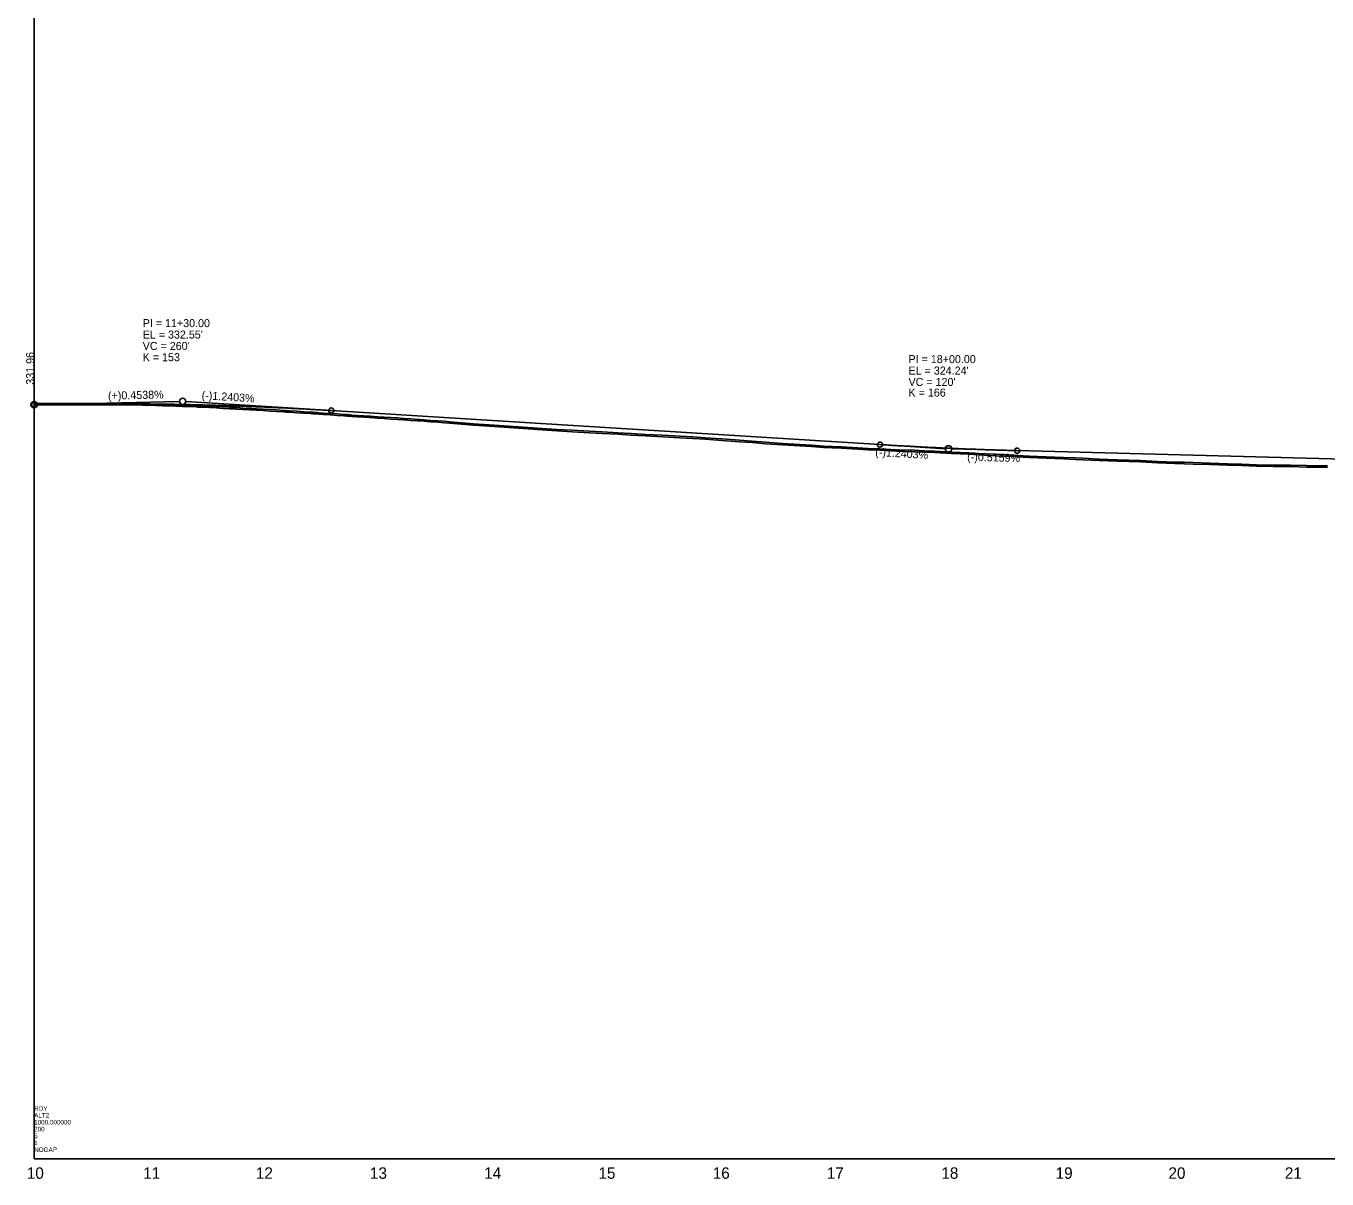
# Model space of a CAD drawing. Extents: x 2111382 to 2119088, y 667477 to 672158.
# Drawn here: x 2112692 to 2113830, y 667477 to 668486 of the extents above; entities that cross this region are included whole.
import ezdxf

# ---------------------------------------------------------------- set-up
doc = ezdxf.new("R2010")
doc.units = 0
for name, color, linetype in [('Exist Profile Cell', 7, 'Continuous'), ('Exist Vertical Profile Ground Line', 7, 'Continuous'), ('Exist Vertical Profile Horizontal Axis Label Major', 7, 'Continuous'), ('Prop Vertical Profile Curve Label', 7, 'Continuous'), ('Prop Vertical Profile Grade', 7, 'Continuous'), ('Prop Vertical Profile Grade Label', 7, 'Continuous'), ('Prop VPI Label', 7, 'Continuous'), ('Scratch_Level_2', 7, 'Continuous')]:
    doc.layers.add(name, color=color, linetype=linetype)

msp = doc.modelspace()

# ---------------------------------------------------------------- linework, layer by layer
at = {"layer": 'Exist Profile Cell'}
for q in [(2112699, 669494.5), (2114955.5, 667494.5), (2112699, 667494.5)]:
    msp.add_line((2112699, 667494.5), q, dxfattribs=at)
at = {"layer": 'Exist Vertical Profile Ground Line'}
for points in [[(2112699, 668154.3), (2112711.5, 668154.3), (2112717.4, 668154.3), (2112723.2, 668154.3), (2112729.1, 668154.3), (2112735, 668154.3), (2112740.8, 668154.3), (2112746.7, 668154.3), (2112752.6, 668154.3), (2112758.5, 668154.3), (2112759, 668154.3), (2112762.3, 668154.3), (2112764.3, 668154.3), (2112770.2, 668154.3), (2112776.1, 668154.2), (2112781.9, 668154.2), (2112785.4, 668154.2), (2112787.8, 668154.1), (2112793.7, 668153.9), (2112799.6, 668153.8), (2112805.4, 668153.6), (2112811.3, 668153.4), (2112814.5, 668153.3), (2112815.4, 668153.2), (2112816.2, 668153.2), (2112817.2, 668153.2), (2112823, 668153), (2112828.9, 668152.8), (2112834.8, 668152.6), (2112840.7, 668152.4), (2112842.2, 668152.3), (2112846.5, 668152.1), (2112852.4, 668151.8), (2112858.3, 668151.5), (2112864.2, 668151.1), (2112870, 668150.8), (2112870.4, 668150.8), (2112872.2, 668150.7), (2112875.9, 668150.5), (2112881.8, 668150.2), (2112887.6, 668149.9), (2112889.6, 668149.8), (2112893.1, 668149.5), (2112893.5, 668149.5), (2112899.4, 668149.2), (2112905.3, 668148.8), (2112911.1, 668148.4), (2112917, 668148.1), (2112919.6, 668147.9), (2112922.9, 668147.7), (2112928.7, 668147.3), (2112934.6, 668146.9), (2112940.5, 668146.6), (2112942.8, 668146.4), (2112946.4, 668146.2), (2112948.1, 668146), (2112952.2, 668145.8), (2112958.1, 668145.4), (2112964, 668145), (2112969.9, 668144.6), (2112972.8, 668144.4), (2112975.7, 668144.2), (2112977, 668144.1), (2112981.6, 668143.8), (2112987.5, 668143.4), (2112992.1, 668143.1), (2112993.3, 668143), (2112999.2, 668142.6), (2112999.6, 668142.6), (2113005.1, 668142.2), (2113011, 668141.8), (2113016.8, 668141.4), (2113022.1, 668141.1), (2113022.7, 668141), (2113028.6, 668140.6), (2113034.4, 668140.2), (2113036.4, 668140.1), (2113040.3, 668139.8), (2113043, 668139.6), (2113046.2, 668139.4), (2113052.1, 668139), (2113057.9, 668138.5), (2113062.5, 668138.2), (2113073, 668137.3), (2113083.5, 668136.4), (2113101.4, 668135.1), (2113114.3, 668134.3), (2113131.3, 668133.1), (2113143.3, 668132.2), (2113156.2, 668131.5), (2113169.6, 668130.7), (2113180, 668130.1), (2113195.9, 668129.2), (2113210, 668128.4), (2113221.4, 668127.8), (2113234, 668127.1), (2113248.9, 668126.3), (2113264, 668125.4), (2113275.4, 668124.8), (2113286.1, 668124.2), (2113300.7, 668123.1)], [(2113300.7, 668123.1), (2113316.1, 668121.9), (2113327.3, 668121.1), (2113338.9, 668120.2), (2113353.8, 668119.3), (2113368.9, 668118.2), (2113379.2, 668117.6), (2113389.6, 668116.9), (2113405.1, 668116.2), (2113419.6, 668115.4), (2113428.8, 668114.8), (2113438.9, 668114.4), (2113453.4, 668113.7), (2113468.9, 668113.2), (2113477.6, 668112.7), (2113486.8, 668112.4), (2113501.6, 668111.7), (2113516.8, 668110.9), (2113525.1, 668110.4), (2113539.8, 668109.6), (2113554.8, 668108.9), (2113564.4, 668108.4), (2113569.5, 668108.1), (2113584.5, 668107.4), (2113599.6, 668106.9), (2113609.8, 668106.4), (2113616.5, 668106.1), (2113631.2, 668105.6), (2113646.5, 668105), (2113656.8, 668104.5), (2113667, 668104.2), (2113681.9, 668103.5), (2113697, 668102.8), (2113705.4, 668102.7), (2113713.1, 668102.3), (2113728, 668101.9), (2113743.1, 668101.3), (2113755.7, 668101), (2113768.5, 668100.5), (2113782.9, 668100.2), (2113798.5, 668100.1), (2113812.1, 668099.8), (2113828.6, 668099.7), (2113830.4, 668099.7)]]:
    msp.add_lwpolyline(points, dxfattribs=at)
at = {"layer": 'Prop Vertical Profile Curve Label'}
for centre in [(2112699, 668154.3), (2112959, 668149.2), (2113439, 668119.4), (2113559, 668114.1)]:
    msp.add_circle(centre, 2.25, dxfattribs=at)
at = {"layer": 'Prop Vertical Profile Grade'}
for p, q in [((2112959, 668149.2), (2113439, 668119.4)), ((2113559, 668114.1), (2113879, 668105.9))]:
    msp.add_line(p, q, dxfattribs=at)
for points in [[(2112699, 668154.3), (2112704.2, 668154.4), (2112709.4, 668154.5), (2112714.6, 668154.6), (2112719.8, 668154.7), (2112725, 668154.8), (2112730.2, 668154.8), (2112735.4, 668154.9), (2112740.6, 668154.9), (2112745.8, 668155), (2112751, 668155), (2112756.2, 668155), (2112761.4, 668155.1), (2112766.6, 668155.1), (2112771.8, 668155.1), (2112777, 668155.1), (2112782.2, 668155), (2112787.4, 668155), (2112792.6, 668155), (2112797.8, 668154.9), (2112803, 668154.9), (2112808.2, 668154.8), (2112813.4, 668154.7), (2112818.6, 668154.7), (2112823.8, 668154.6), (2112829, 668154.5), (2112834.2, 668154.4), (2112839.4, 668154.2), (2112844.6, 668154.1), (2112849.8, 668154), (2112855, 668153.9), (2112860.2, 668153.7), (2112865.4, 668153.5), (2112870.6, 668153.4), (2112875.8, 668153.2), (2112881, 668153), (2112886.2, 668152.8), (2112891.4, 668152.6), (2112896.6, 668152.4), (2112901.8, 668152.2), (2112907, 668151.9), (2112912.2, 668151.7), (2112917.4, 668151.5), (2112922.6, 668151.2), (2112927.8, 668150.9), (2112933, 668150.7), (2112938.2, 668150.4), (2112943.4, 668150.1), (2112948.6, 668149.8), (2112953.8, 668149.5), (2112959, 668149.2)], [(2113439, 668119.4), (2113441.4, 668119.2), (2113443.8, 668119.1), (2113446.2, 668119), (2113448.6, 668118.8), (2113451, 668118.7), (2113453.4, 668118.5), (2113455.8, 668118.4), (2113458.2, 668118.3), (2113460.6, 668118.1), (2113463, 668118), (2113465.4, 668117.9), (2113467.8, 668117.7), (2113470.2, 668117.6), (2113472.6, 668117.5), (2113475, 668117.4), (2113477.4, 668117.2), (2113479.8, 668117.1), (2113482.2, 668117), (2113484.6, 668116.9), (2113487, 668116.8), (2113489.4, 668116.7), (2113491.8, 668116.5), (2113494.2, 668116.4), (2113496.6, 668116.3), (2113499, 668116.2), (2113501.4, 668116.1), (2113503.8, 668116), (2113506.2, 668115.9), (2113508.6, 668115.8), (2113511, 668115.7), (2113513.4, 668115.6), (2113515.8, 668115.5), (2113518.2, 668115.4), (2113520.6, 668115.3), (2113523, 668115.3), (2113525.4, 668115.2), (2113527.8, 668115.1), (2113530.2, 668115), (2113532.6, 668114.9), (2113535, 668114.8), (2113537.4, 668114.8), (2113539.8, 668114.7), (2113542.2, 668114.6), (2113544.6, 668114.5), (2113547, 668114.5), (2113549.4, 668114.4), (2113551.8, 668114.3), (2113554.2, 668114.3), (2113556.6, 668114.2), (2113559, 668114.1)]]:
    msp.add_spline(points, degree=3, dxfattribs=at)
at = {"layer": 'Prop VPI Label'}
for p, q in [((2112699, 668154.3), (2112826.3, 668157.2)), ((2112959, 668149.2), (2112831.7, 668157.1)), ((2113439, 668119.4), (2113496.3, 668115.8)), ((2113559, 668114.1), (2113501.8, 668115.6))]:
    msp.add_line(p, q, dxfattribs=at)
for centre in [(2112699, 668154.3), (2112829, 668157.2), (2113499, 668115.7)]:
    msp.add_circle(centre, 2.75, dxfattribs=at)
at = {"layer": 'Scratch_Level_2'}
for points in [[(2112699, 668155.5), (2112711.5, 668155.5), (2112717.4, 668155.5), (2112723.2, 668155.5), (2112729.1, 668155.5), (2112735, 668155.5), (2112740.8, 668155.5), (2112746.7, 668155.5), (2112752.6, 668155.5), (2112758.5, 668155.5), (2112759, 668155.5), (2112762.3, 668155.5), (2112764.3, 668155.5), (2112770.2, 668155.5), (2112776.1, 668155.5), (2112781.9, 668155.5), (2112785.4, 668155.5), (2112787.8, 668155.4), (2112793.7, 668155.2), (2112799.6, 668155), (2112805.4, 668154.8), (2112811.3, 668154.6), (2112814.5, 668154.5), (2112815.4, 668154.5), (2112816.2, 668154.5), (2112817.2, 668154.4), (2112823, 668154.2), (2112828.9, 668154), (2112834.8, 668153.8), (2112840.7, 668153.6), (2112842.2, 668153.5), (2112846.5, 668153.3), (2112852.4, 668153), (2112858.3, 668152.7), (2112864.2, 668152.4), (2112870, 668152.1), (2112870.4, 668152.1), (2112872.2, 668152), (2112875.9, 668151.8), (2112881.8, 668151.4), (2112887.6, 668151.1), (2112889.6, 668151), (2112893.1, 668150.8), (2112893.5, 668150.8), (2112899.4, 668150.4), (2112905.3, 668150), (2112911.1, 668149.7), (2112917, 668149.3), (2112919.6, 668149.1), (2112922.9, 668148.9), (2112928.7, 668148.6), (2112934.6, 668148.2), (2112940.5, 668147.8), (2112942.8, 668147.7), (2112946.4, 668147.4), (2112948.1, 668147.3), (2112952.2, 668147), (2112958.1, 668146.6), (2112964, 668146.2), (2112969.9, 668145.8), (2112972.8, 668145.6), (2112975.7, 668145.4), (2112977, 668145.3), (2112981.6, 668145), (2112987.5, 668144.6), (2112992.1, 668144.3), (2112993.3, 668144.2), (2112999.2, 668143.8), (2112999.6, 668143.8), (2113005.1, 668143.5), (2113011, 668143.1), (2113016.8, 668142.7), (2113022.1, 668142.3), (2113022.7, 668142.3), (2113028.6, 668141.9), (2113034.4, 668141.5), (2113036.4, 668141.3), (2113040.3, 668141.1), (2113043, 668140.9), (2113046.2, 668140.6), (2113052.1, 668140.2), (2113057.9, 668139.8), (2113062.5, 668139.4), (2113073, 668138.5), (2113083.5, 668137.7), (2113101.4, 668136.3), (2113114.3, 668135.6), (2113131.3, 668134.3), (2113143.3, 668133.5), (2113156.2, 668132.7), (2113169.6, 668131.9), (2113180, 668131.4), (2113195.9, 668130.5), (2113210, 668129.7), (2113221.4, 668129.1), (2113234, 668128.3), (2113248.9, 668127.6), (2113264, 668126.7), (2113275.4, 668126.1), (2113286.1, 668125.4), (2113300.7, 668124.4)], [(2113300.7, 668124.4), (2113316.1, 668123.2), (2113327.3, 668122.4), (2113338.9, 668121.5), (2113353.8, 668120.5), (2113368.9, 668119.5), (2113379.2, 668118.8), (2113389.6, 668118.1), (2113405.1, 668117.4), (2113419.6, 668116.6), (2113428.8, 668116.1), (2113438.9, 668115.6), (2113453.4, 668114.9), (2113468.9, 668114.4), (2113477.6, 668114), (2113486.8, 668113.7), (2113501.6, 668112.9), (2113516.8, 668112.1), (2113525.1, 668111.7), (2113539.8, 668110.9), (2113554.8, 668110.1), (2113564.4, 668109.6), (2113569.5, 668109.4), (2113584.5, 668108.7), (2113599.6, 668108.1), (2113609.8, 668107.7), (2113616.5, 668107.4), (2113631.2, 668106.8), (2113646.5, 668106.2), (2113656.8, 668105.8), (2113667, 668105.4), (2113681.9, 668104.7), (2113697, 668104.1), (2113705.4, 668103.9), (2113713.1, 668103.6), (2113728, 668103.1), (2113743.1, 668102.6), (2113755.7, 668102.2), (2113768.5, 668101.8), (2113782.9, 668101.5), (2113798.5, 668101.3), (2113812.1, 668101.1), (2113828.6, 668100.9), (2113830.4, 668100.9)]]:
    msp.add_lwpolyline(points, dxfattribs=at)

# ---------------------------------------------------------------- texts
at = {"layer": 'Exist Profile Cell'}
for s, p in [('RDY', (2112699, 667536.5)), ('ALT2', (2112699, 667530.5)), ('1000.000000', (2112699, 667524.5)), ('5', (2112699, 667512.5)), ('200', (2112699, 667518.5)), ('1', (2112699, 667506.5)), ('NOGAP', (2112699, 667500.5))]:
    msp.add_text(s, height=4, dxfattribs=at).set_placement(p)
at = {"layer": 'Exist Vertical Profile Horizontal Axis Label Major'}
for s, p in [('10', (2112692.6, 667477)), ('11', (2112794.4, 667477)), ('12', (2112893, 667477)), ('13', (2112992.8, 667477)), ('14', (2113092.7, 667477)), ('15', (2113192.7, 667477)), ('16', (2113292.7, 667477)), ('17', (2113392.5, 667477)), ('18', (2113492.7, 667477)), ('19', (2113592.7, 667477)), ('20', (2113691.4, 667477)), ('21', (2113793.2, 667477))]:
    msp.add_text(s, height=10, dxfattribs=at).set_placement(p)
at = {"layer": 'Prop Vertical Profile Curve Label'}
for s, p in [("VC = 260'", (2112794, 668202.2)), ('K = 153', (2112794, 668192.4)), ("VC = 120'", (2113464, 668170.7)), ('K = 166', (2113464, 668161.4))]:
    msp.add_text(s, height=7, dxfattribs=at).set_placement(p)
at = {"layer": 'Prop Vertical Profile Grade Label'}
for s, rotation, p in [('(+)0.4538%', 1.3, (2112763.7, 668158.7)), ('(-)1.2403%', 356.4514, (2112845.4, 668159.2)), ('(-)1.2403%', 356.4514, (2113434.7, 668109.6)), ('(-)0.5159%', 358.5225, (2113515.2, 668105.3))]:
    msp.add_text(s, height=7, rotation=rotation, dxfattribs=at).set_placement(p)
at = {"layer": 'Prop VPI Label'}
for s, p in [('PI = 11+30.00', (2112794, 668222.2)), ("EL = 332.55'", (2112794, 668212.2)), ('PI = 18+00.00', (2113464, 668190.7)), ("EL = 324.24'", (2113464, 668180.7))]:
    msp.add_text(s, height=7, dxfattribs=at).set_placement(p)
msp.add_text('331.96', height=7, rotation=90, dxfattribs=at).set_placement((2112699, 668171.8))

doc.saveas('drawing.dxf')
